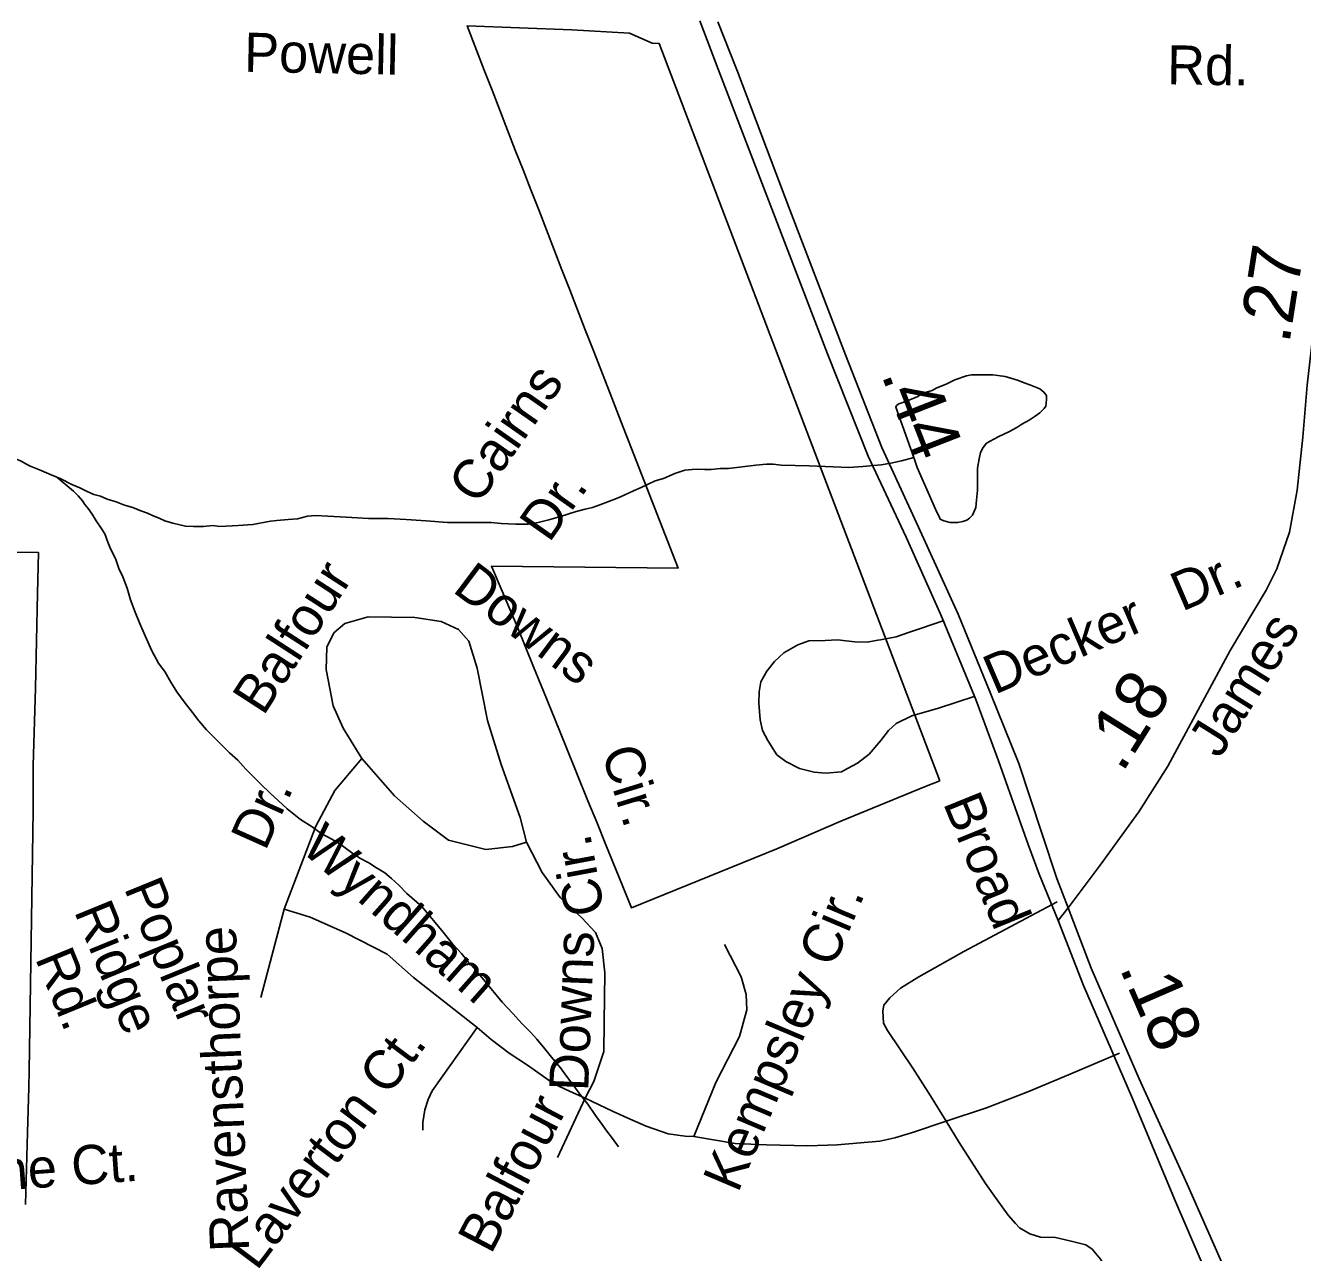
# Model space of a CAD drawing. Extents: x 2001466 to 2224147, y 644118 to 847247.
# Drawn here: x 2055654 to 2058752, y 674300 to 677277 of the extents above; entities that cross this region are included whole.
import ezdxf

# ---------------------------------------------------------------- set-up
doc = ezdxf.new("R2010")
doc.units = 0
for name, color, linetype in [('Exist Boundary Political City Limit New', 7, 'Continuous'), ('Exist Hydrographic Misc Water Feature', 7, 'Continuous'), ('Exist Road Non-System Type 51', 7, 'Continuous'), ('Exist Road Non-System Type 51 Label', 7, 'Continuous'), ('Exist Road Primary NC Divided Attributed', 7, 'Continuous'), ('Exist Road Primary NC Label', 7, 'Continuous'), ('Exist Road Primary NC Service Mileage Hundredths English Label', 7, 'Continuous'), ('Exist Road Secondary Mileage Hundredths English Label', 7, 'Continuous'), ('Exist Road Secondary Type 51 Attributed', 7, 'Continuous'), ('Exist Road Secondary Type 51 Label', 7, 'Continuous'), ('Map Preparation Boundary City Limit Buffer Line', 7, 'Continuous')]:
    doc.layers.add(name, color=color, linetype=linetype)

msp = doc.modelspace()

# ---------------------------------------------------------------- linework, layer by layer
at = {"layer": 'Exist Boundary Political City Limit New'}
for points in [[(2057872.1, 675444.5), (2057677.1, 675956.6), (2057638.2, 676058.7), (2057190.8, 677233.8), (2057174.4, 677234.3), (2057119.4, 677259), (2056979.1, 677266.8), (2056725.1, 677276.4), (2056748.1, 677217.6), (2056766.9, 677169.1), (2056785.8, 677120.7), (2056804.6, 677072.2), (2056823.5, 677023.7), (2056842.2, 676975.2), (2056861.1, 676926.8), (2056880, 676878.4), (2056898.9, 676829.8), (2056917.6, 676781.4), (2056936.5, 676733), (2056955.4, 676684.4), (2056974.2, 676636), (2056993, 676587.6), (2057011.9, 676539.1), (2057030.8, 676490.6), (2057049.6, 676442.2), (2057076, 676374.1), (2057092.4, 676332.1), (2057148.1, 676188.8), (2057237.1, 675960.3), (2056784.2, 675964.9), (2056847.4, 675817.5), (2056886.4, 675721.3), (2056910.6, 675661.7), (2056938.8, 675592.2), (2056964.6, 675528.5), (2056991.8, 675461.8), (2057018.4, 675396.2), (2057039.8, 675343.7), (2057061.9, 675289.3), (2057094, 675210), (2057124.1, 675135.9), (2057476.9, 675279.1), (2057632.2, 675346.8), (2057834.9, 675429.9), (2057872.1, 675444.5)], [(2055408.4, 676001.1), (2055685.5, 675998.2), (2055682.9, 675899)], [(2055682.9, 675899), (2055678.1, 675668.9), (2055672.8, 675481.8), (2055672.6, 675371.5), (2055663, 674740.8), (2055662.2, 674700.2), (2055659.1, 674590.8), (2055653.9, 674415.9)]]:
    msp.add_lwpolyline(points, dxfattribs=at)
at = {"layer": 'Exist Hydrographic Misc Water Feature'}
for points in [[(2057809.4, 676229.2), (2057817.2, 676204.9), (2057861.5, 676103.3), (2057867.6, 676091.4), (2057869.5, 676087.1), (2057871.3, 676083.2), (2057873.2, 676079.2), (2057881.4, 676075.1), (2057897.4, 676071.5), (2057915.2, 676071.2), (2057927.5, 676073.4), (2057937.6, 676077.2), (2057943.7, 676081.5), (2057951.3, 676089.3), (2057959.1, 676107.6), (2057961.4, 676125.5), (2057963.6, 676149.5), (2057963.4, 676163.3), (2057963.2, 676177.5), (2057963.2, 676203.5), (2057967.3, 676225.6), (2057970.8, 676241.3), (2057977.1, 676253.3), (2057985.1, 676263.5), (2058003, 676273.3), (2058015.1, 676279.6), (2058027, 676285.5), (2058039.1, 676291.4), (2058059.2, 676301.7), (2058071.1, 676309.7), (2058088.9, 676319.5), (2058100.8, 676327.8), (2058109, 676333.5), (2058114.7, 676337.5), (2058125, 676347.7), (2058128.9, 676353.6), (2058130.7, 676369.5), (2058130.7, 676379.7), (2058124.8, 676387.9), (2058114.7, 676395.5), (2058090.7, 676405.6), (2058076.6, 676409.8), (2058062.6, 676415.5), (2058044.6, 676421.5), (2058030.9, 676425.7), (2058012.8, 676427.6), (2058000.9, 676429.4), (2057992.7, 676429.4), (2057980.8, 676429.6), (2057964.8, 676429.6), (2057949.1, 676429.5), (2057936.7, 676427.4), (2057908.7, 676417.4), (2057888.8, 676407.4), (2057862.9, 676397.2), (2057853.1, 676391.4), (2057831.1, 676385), (2057818.6, 676377.1), (2057799.2, 676369.1), (2057785, 676363.1), (2057772.7, 676358.9), (2057767, 676354.9), (2057765.1, 676351.1), (2057809.4, 676229.2)], [(2055729.8, 676181.1), (2055715.8, 676187.3), (2055687.7, 676199.3), (2055663.7, 676209), (2055641.6, 676221.3), (2055617.6, 676231), (2055587.5, 676249), (2055561.8, 676263)], [(2057809.4, 676229.2), (2057779.1, 676221.3), (2057753, 676215.1), (2057729.4, 676211), (2057684.9, 676207.1), (2057651.5, 676204.9), (2057613.6, 676206.6), (2057555.1, 676208.6), (2057487.5, 676210.3), (2057467.4, 676212.6), (2057451.2, 676212.6), (2057425.3, 676210.4), (2057359.3, 676202.2), (2057339, 676202.4), (2057317.5, 676200), (2057301.3, 676200), (2057283.5, 676200.3), (2057271.6, 676200.1), (2057253.3, 676197.9), (2057229.5, 676190.2), (2057201.4, 676177.8), (2057181.3, 676172), (2057147.7, 676156), (2057129.3, 676147.8), (2057097.7, 676133.9), (2057083.5, 676128), (2057047.6, 676113.9), (2057029.6, 676107.8), (2057011.6, 676103.6), (2056989.6, 676097.6), (2056951.5, 676085.5), (2056923.8, 676077.6), (2056897.7, 676071.4), (2056873.6, 676067.3), (2056843.4, 676067.4), (2056807.7, 676069.2), (2056783.7, 676071.2), (2056760, 676071.2), (2056717.9, 676071.1), (2056677.9, 676071), (2056625.8, 676074.9), (2056577.7, 676078.9), (2056533.8, 676080.7), (2056515.9, 676080.6), (2056485.6, 676080.7), (2056459.6, 676082.6), (2056431.5, 676084.5), (2056387.6, 676086.7), (2056357.6, 676088.3), (2056338, 676086.5), (2056314, 676080.4), (2056291.4, 676078.5), (2056263.9, 676076.2), (2056247.9, 676074.2), (2056205.7, 676066.4), (2056169.6, 676064.2), (2056125.5, 676061.9), (2056108.1, 676064.2), (2056085.5, 676061.9), (2056061.8, 676061.8), (2056041.9, 676062.1), (2056011.7, 676069.8), (2055991.8, 676075.7), (2055977.9, 676081.8), (2055963.5, 676087.7), (2055949.8, 676093.8), (2055933.8, 676099.5), (2055913.9, 676107.8), (2055894, 676113.6), (2055873.7, 676121.6), (2055851.8, 676127.8), (2055836, 676135.4), (2055819.6, 676139.5), (2055801.9, 676147.5), (2055785.8, 676155.2), (2055765.9, 676163.5), (2055739.6, 676177.2), (2055729.8, 676181.1)], [(2057092.3, 674556.1), (2057078.2, 674576.1), (2057064.3, 674594.1), (2057050.5, 674614), (2057036.4, 674632), (2057018.1, 674659.9), (2056998.4, 674684), (2056984.3, 674703.9), (2056966.2, 674727.8), (2056952.1, 674747.8), (2056930.1, 674773.8), (2056913.7, 674793.8), (2056894.1, 674817.8), (2056880.1, 674833.7), (2056857.8, 674855.8), (2056835.8, 674879.4), (2056810, 674907.6), (2056783.7, 674939.6), (2056765.7, 674961.4), (2056747.6, 674983.2), (2056727.6, 675005.3), (2056711.4, 675025.2), (2056689.4, 675049.2), (2056667.5, 675077.3), (2056643.5, 675105.2), (2056615.2, 675139.2), (2056579.3, 675170.9), (2056559.2, 675191), (2056541.6, 675207.1), (2056525.6, 675220.9), (2056505.5, 675232.9), (2056487, 675245), (2056465.3, 675256.8), (2056445, 675270.8), (2056416.9, 675290.9), (2056397.2, 675302.8), (2056371, 675316.5), (2056349, 675332.8), (2056320.9, 675350.5), (2056288.7, 675376.4), (2056267, 675396.3), (2056247.1, 675414.4), (2056224.8, 675436.4), (2056206.9, 675454.1), (2056188.7, 675472.3), (2056168.6, 675494.4), (2056149.1, 675512), (2056129, 675532.1), (2056110.8, 675550.2), (2056092.9, 675568), (2056074.5, 675590.2), (2056058.7, 675610.1), (2056038.8, 675635.8), (2056020.7, 675660), (2056006.4, 675684.1), (2055992.4, 675707.7), (2055976.7, 675730), (2055960.5, 675759.6), (2055950.4, 675781.8), (2055940.6, 675803.6), (2055930.5, 675827.8), (2055920.3, 675853.7), (2055908.4, 675883.5), (2055900.2, 675911.5), (2055889.9, 675939.4), (2055880.3, 675959.6), (2055871.9, 675983.6), (2055860.2, 676007.7), (2055853.8, 676023.6), (2055846.2, 676043.4), (2055837.8, 676057.6), (2055825.5, 676075.3), (2055815.9, 676091.4), (2055805.8, 676105.5), (2055797.8, 676115.3), (2055791.9, 676123.5), (2055781.6, 676135.6), (2055770, 676147.5), (2055729.8, 676181.1)]]:
    msp.add_lwpolyline(points, dxfattribs=at)
at = {"layer": 'Exist Road Non-System Type 51'}
for p, q in [((2056281.7, 675132.7), (2056224.5, 674918.5)), ((2057011.4, 674674.4), (2056944.5, 674530.5))]:
    msp.add_line(p, q, dxfattribs=at)
for points in [[(2056470.1, 675498.6), (2056424.7, 675571.9), (2056400.6, 675626.7), (2056383.3, 675714.9), (2056384.6, 675768.4), (2056402, 675803.2), (2056428.7, 675825.9), (2056484.8, 675842), (2056598.4, 675840.6), (2056662.6, 675831.3), (2056704, 675811.2), (2056729.4, 675783.1), (2056749.4, 675717.6), (2056774.8, 675590.6), (2056808.2, 675483.6), (2056853.7, 675355.2), (2056869.7, 675295.3)], [(2057882.3, 675833.2), (2057798.5, 675805), (2057766.2, 675793.7), (2057728.1, 675786.5), (2057721.9, 675785.4)], [(2057721.9, 675785.4), (2057696, 675781.1), (2057666, 675781.7), (2057624.1, 675786.6), (2057594.1, 675785.2), (2057554.1, 675784), (2057527.9, 675774.5), (2057493.5, 675755.2), (2057471, 675733.7), (2057452.5, 675710.1), (2057438, 675684.4), (2057433.5, 675660.5), (2057433, 675632.5), (2057436.2, 675592.4), (2057441.6, 675566.3), (2057455.1, 675542), (2057476.4, 675507.6), (2057498.1, 675491.1), (2057531.8, 675474.5), (2057567.6, 675465.7), (2057595.5, 675463.2), (2057633.6, 675466.4), (2057647.7, 675474.1), (2057672, 675487.6), (2057700.5, 675509), (2057729.1, 675542.5), (2057747.6, 675566.1), (2057766, 675583.7), (2057804, 675601.8)], [(2057804, 675601.8), (2057806.4, 675602.9), (2057866.7, 675619.7), (2057957.8, 675649.6)], [(2056281.7, 675132.7), (2056357.9, 675334.1), (2056404.7, 675421), (2056470.1, 675498.6)], [(2056470.1, 675498.6), (2056549, 675407.7), (2056618.5, 675346.2), (2056679.9, 675300.7), (2056770.8, 675278), (2056835, 675284.6), (2056869.7, 675295.3)], [(2056869.7, 675295.3), (2056907.1, 675221.8), (2056951.2, 675161.6), (2057003.4, 675112.2), (2057036.8, 675076), (2057052.8, 675037.3), (2057059.5, 674978.4), (2057058.1, 674858.1), (2057056.8, 674787.2), (2057032.8, 674714.5), (2057011.4, 674674.4)], [(2056281.7, 675132.7), (2056344.2, 675113.2), (2056430.3, 675075.8), (2056531.3, 675023.4), (2056595, 674967.2), (2056749.5, 674845.5)], [(2058156.8, 675150.4), (2057930.7, 675030.4), (2057821.5, 674968.6), (2057776.9, 674941.5), (2057750.4, 674918), (2057736.1, 674900.3), (2057733.8, 674886.4), (2057735.2, 674856.3), (2057744.8, 674838.1), (2057806.9, 674746.9), (2057849.6, 674680), (2057887.4, 674618.5)], [(2057275.2, 674581.6), (2057328.6, 674712.6), (2057386.1, 674823.6), (2057403.5, 674888.3), (2057402.1, 674925.8), (2057390.1, 674968.5), (2057350, 675047.4)], [(2056749.5, 674845.5), (2056640.6, 674691.9), (2056630.8, 674670.9), (2056622.4, 674645.8), (2056618.2, 674615), (2056618.2, 674596.9)], [(2056749.5, 674845.5), (2056783.7, 674816.9), (2056827, 674783.4), (2056871.7, 674754), (2056935.9, 674709.3), (2056974, 674690.9), (2057011.4, 674674.4)], [(2057887.4, 674618.5), (2057985.3, 674651.1), (2058085.6, 674689.9), (2058184.4, 674731.3), (2058307.8, 674783.7)], [(2057011.4, 674674.4), (2057079.5, 674642.3), (2057121, 674623.6), (2057159.7, 674606.2), (2057213.2, 674587.5), (2057254.6, 674582.1), (2057275.2, 674581.6)], [(2057275.2, 674581.6), (2057375.8, 674564.1), (2057451.2, 674561.3), (2057551.8, 674558.5), (2057623, 674561.3), (2057726.4, 674569.6), (2057762.7, 674578), (2057806, 674590.6), (2057887.4, 674618.5)], [(2057887.4, 674618.5), (2057919.3, 674566.6), (2057983.2, 674467.3), (2058008.5, 674430.8), (2058037.7, 674390.2), (2058055.3, 674369.8), (2058065.1, 674359.6), (2058090.8, 674345.1), (2058116.6, 674336.6), (2058152.6, 674335.8), (2058190.4, 674327.1), (2058226.2, 674318.4), (2058242, 674308), (2058249.8, 674297.9), (2058261.5, 674283.6), (2058277, 674257.3), (2058339, 674151.8)]]:
    msp.add_lwpolyline(points, dxfattribs=at)
at = {"layer": 'Exist Road Primary NC Divided Attributed'}
for points in [[(2058158.8, 675105.7), (2058112.9, 675217.9), (2058086.4, 675289.6), (2058014.4, 675493.1), (2057959.6, 675641.7), (2057874.5, 675847.4), (2057790.5, 676036), (2057698, 676232.6), (2057599.5, 676480.8), (2057464.4, 676832.6), (2057334.1, 677171.6), (2057289.7, 677288.9)], [(2058183.1, 675136.2), (2058156.1, 675207.5), (2058119.5, 675317.1), (2058063.5, 675486.2), (2057993.9, 675658.8), (2057916.7, 675848.5), (2057820.2, 676060), (2057731.1, 676253.2), (2057643.4, 676478.3), (2057508.3, 676830.1), (2057381.5, 677165.3), (2057333.6, 677286.4)], [(2058571, 674242.1), (2058472.5, 674465.3), (2058355.8, 674721.4), (2058239.1, 674989.7), (2058183.1, 675136.2)], [(2058528.9, 674226), (2058444.1, 674423.4), (2058336.9, 674679.1), (2058220.3, 674947.4), (2058158.8, 675105.7)]]:
    msp.add_lwpolyline(points, dxfattribs=at)
at = {"layer": 'Exist Road Secondary Type 51 Attributed'}
for points in [[(2058183.1, 675136.2), (2058261.4, 675239.4), (2058354.7, 675369), (2058425.3, 675480.2), (2058576.8, 675760.7), (2058663.9, 675907.3), (2058689.7, 675958.9), (2058720.7, 676048), (2058739.2, 676149.4), (2058752.7, 676278.4), (2058763.1, 676404.4), (2058789.5, 676631.1), (2058814.7, 676715.3), (2058856.8, 676810.5), (2058933.5, 676957.4), (2058987.6, 677043.4), (2059037.9, 677104.2), (2059127.9, 677195.2), (2059220, 677278.1)], [(2058158.8, 675105.7), (2058183.1, 675136.2)]]:
    msp.add_lwpolyline(points, dxfattribs=at)
at = {"layer": 'Map Preparation Boundary City Limit Buffer Line'}
for points in [[(2057872.1, 675444.5), (2057677.1, 675956.6), (2057638.2, 676058.7), (2057190.8, 677233.8), (2057174.4, 677234.3), (2057119.4, 677259), (2056979.1, 677266.8), (2056725.1, 677276.4), (2056748.1, 677217.6), (2056766.9, 677169.1), (2056785.8, 677120.7), (2056804.6, 677072.2), (2056823.5, 677023.7), (2056842.2, 676975.2), (2056861.1, 676926.8), (2056880, 676878.4), (2056898.9, 676829.8), (2056917.6, 676781.4), (2056936.5, 676733), (2056955.4, 676684.4), (2056974.2, 676636), (2056993, 676587.6), (2057011.9, 676539.1), (2057030.8, 676490.6), (2057049.6, 676442.2), (2057076, 676374.1), (2057092.4, 676332.1), (2057148.1, 676188.8), (2057237.1, 675960.3), (2056784.2, 675964.9), (2056847.4, 675817.5), (2056886.4, 675721.3), (2056910.6, 675661.7), (2056938.8, 675592.2), (2056964.6, 675528.5), (2056991.8, 675461.8), (2057018.4, 675396.2), (2057039.8, 675343.7), (2057061.9, 675289.3), (2057094, 675210), (2057124.1, 675135.9), (2057476.9, 675279.1), (2057632.2, 675346.8), (2057834.9, 675429.9), (2057872.1, 675444.5)], [(2055408.4, 676001.1), (2055685.5, 675998.2), (2055682.9, 675899)], [(2055682.9, 675899), (2055678.1, 675668.9), (2055672.8, 675481.8), (2055672.6, 675371.5), (2055663, 674740.8), (2055662.2, 674700.2), (2055659.1, 674590.8), (2055653.9, 674415.9)]]:
    msp.add_lwpolyline(points, dxfattribs=at)

# ---------------------------------------------------------------- texts
at = {"layer": 'Exist Road Non-System Type 51 Label'}
for s, rotation, p in [('Cairns', 54.9594, (2056752, 676111)), ('Dr.', 54.9594, (2056924.4, 676019.9)), ('Balfour', 57.1005, (2056230.9, 675599.7)), ('Downs', 323.1241, (2056687, 675904.8)), ('Dr.', 23.3, (2058459.4, 675854.4)), ('Decker', 23.3, (2058005.1, 675652.9)), ('Cir.', 287.0992, (2057050.6, 675514.5)), ('Dr.', 65.8795, (2056235.6, 675272)), ('Wyndham', 318.5701, (2056318.5, 675276.8)), ('Cir.', 100.5641, (2057059.3, 675125.4)), ('Poplar', 292.2504, (2055892, 675184.4)), ('Kempsley Cir.', 67.0158, (2057382.2, 674442.1)), ('Ridge', 292.2504, (2055770.8, 675128.3)), ('Ravensthorpe', 92.3825, (2056196.9, 674303.3)), ('Downs', 87.7979, (2057019, 674690.2)), ('Rd.', 292.2504, (2055676.3, 675014.1)), ('Laverton Ct.', 53.0975, (2056215, 674253.3)), ('Balfour', 62.3761, (2056783, 674293)), ('Pepperstone Ct.', 4.0909, (2055014.4, 674408.6))]:
    msp.add_text(s, height=95, rotation=rotation, dxfattribs=at).set_placement(p)
at = {"layer": 'Exist Road Primary NC Label'}
msp.add_text('Broad', height=95, rotation=292.0992, dxfattribs=at).set_placement((2057879.1, 675390.9))
at = {"layer": 'Exist Road Primary NC Service Mileage Hundredths English Label'}
for s, rotation, p in [('.44', 291.2922, (2057729.1, 676430.5)), ('.18', 293.4961, (2058306.9, 674990.5))]:
    msp.add_text(s, height=125, rotation=rotation, dxfattribs=at).set_placement(p)
at = {"layer": 'Exist Road Secondary Mileage Hundredths English Label'}
for s, rotation, p in [('.27', 81.1396, (2058719.7, 676502.6)), ('.18', 57.9585, (2058314.6, 675461.4))]:
    msp.add_text(s, height=125, rotation=rotation, dxfattribs=at).set_placement(p)
at = {"layer": 'Exist Road Secondary Type 51 Label'}
for s, rotation, p in [('Powell', 358.874, (2056183.6, 677165.2)), ('Rd.', 359.2652, (2058423.1, 677134.4)), ('James', 57.9585, (2058550.5, 675495.8))]:
    msp.add_text(s, height=95, rotation=rotation, dxfattribs=at).set_placement(p)

doc.saveas('drawing.dxf')
